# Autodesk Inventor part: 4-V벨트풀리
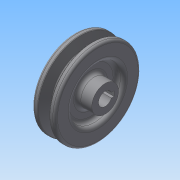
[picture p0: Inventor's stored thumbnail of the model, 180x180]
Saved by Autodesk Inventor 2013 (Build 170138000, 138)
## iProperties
Created: 2015-02
Part Number: 4-V벨트풀리
Material: 일반
Document SubType Name: Modeling
Designer: MYHOME
Density: 1 g/cm^3
Author: MYHOME
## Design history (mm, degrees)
sketch "스케치1"
  geometry: L1 (0, 0)-(25, 0); L2 (25, 0)-(25, 11); L3 (25, 11)-(13, 11); L4 (13, 11)-(13, 21.5); L5 (13, 21.5)-(19, 21.5); L6 (19, 21.5)-(19, 35.2); L7 (19, 35.2)-(14.325, 35.2); L8 (14.325, 35.2)-(11.574, 26.2); L9 (11.574, 26.2)-(7.426, 26.2); L10 (7.426, 26.2)-(4.675, 35.2); L11 (4.675, 35.2)-(0, 35.2); L12 (0, 35.2)-(0, 21.5); L13 (0, 21.5)-(6, 21.5); L14 (6, 21.5)-(6, 11); L15 (6, 11)-(0, 11); L16 (0, 11)-(0, 0); 2 further points
  constraints: 32 end point, 10 parallel, 4 collinear, 3 equal length, 2 perpendicular, 2 point on line, 1 horizontal, 1 horizontal alignment, 1 vertical alignment
  dimensions: "d0" = 25 distance of L1.start L1.end; "d1" = 8 distance of point (13.5, 32.5) point (5.5, 32.5); "d2" = 34 deg angle of L8 L10; "d3" = 19 distance between parallel lines of L6 L12; "d4" = 6 distance of L12.end L13.end; "d6" = 2.7 distance from line of point (5.5, 32.5) L11; "d7" = 6.3 distance from line of L9 point (5.5, 32.5); "d8" = 65 diameter of point (5.5, 32.5) L1; "d9" = 43 diameter of L13 L1; "d10" = 22 diameter of L3 L1
revolve "회전1" sketch "스케치1" stored, may be unused: angle "d11" = 90 deg
sketch "스케치2"
  geometry: L1 (-2, 5.123)-(-2, 7.3); L2 (-2, 7.3)-(2, 7.3); L3 (2, 7.3)-(2, 5.123); C1 r 11 at (0, 0) reference; A1 r 5.5 centre (0, 0) between (-2, 5.123) and (2, 5.123); 1 further point
  constraints: 6 end point, 2 point on circle, 1 centre point, 1 coincident, 1 midpoint, 1 parallel, 1 perpendicular, 1 vertical, 1 vertical alignment
  dimensions: "d12" = 11 diameter of A1; "d14" = 4 distance of L1.end L2.end; "d15" = 12.8 dimension on A1 L2
extrude "돌출1" cut sketch "스케치2" stored distance "d16" = 10; taper "d17" = 0 deg
fillet "모깎기1" dims "d18" = 2, "d19" = 0.5, "d20" = 1, "d21" = 3
node "솔리드1"
